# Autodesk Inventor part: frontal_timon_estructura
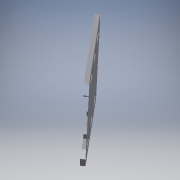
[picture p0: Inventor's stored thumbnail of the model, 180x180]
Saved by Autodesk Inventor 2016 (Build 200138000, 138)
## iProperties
Created: 2017-06
Part Number: frontal_timon_estructura
Material: Generic
Document SubType Name: Modeling
Designer: laboratorioesan
Density: 1 g/cm^3
Appearance: Default
Author: laboratorioesan
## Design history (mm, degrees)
sketch "Sketch1"
  geometry: L1 (-29.189, -4.822)-(-51.614, 22.05) reference; L2 (-47.008, 25.895)-(-22.981, -2.897) reference; L3 (-10.409, -15.199)-(29.692, 18.266) reference; L4 (-43.009, -16.355)-(-65.434, 10.517) reference; L5 (-70.041, 6.673)-(-45.325, -22.944) reference; L6 (-47.008, 25.895)-(-70.041, 6.673) reference; L7 (-31.652, 38.709)-(-432.262, 518.759); L8 (-432.262, 518.759)-(-420.361, 528.69); L9 (-420.361, 528.69)-(-19.752, 48.64); L10 (-31.652, 38.709)-(-19.752, 48.64); L11 (-1131.104, 152.556)-(-641.104, 152.556) reference; L12 (-220.057, 288.665)-(-231.957, 278.734); 1 further point
  constraints: 18 end point, 2 midpoint, 1 parallel, 1 perpendicular, 12 other
  dimensions: "d0" = 20 distance between parallel lines of L7 L2; "d1" = 15.5 distance of L7.end L8.end
extrude "Extrusion1" new body sketch "Sketch1" stored distance "d2" = 200; taper "d3" = 0 deg
sketch "Sketch2"
  geometry: L1 (200, 0)-(0, 0) reference; L2 (0, -312.624)-(0, 0) reference; L3 (200, -312.624)-(0, -312.624) reference; L4 (200, 0)-(200, -312.624) reference; L5 (20, -40)-(35.5, -40); L6 (35.5, -40)-(35.5, -90); L7 (35.5, -90)-(20, -90); L8 (20, -90)-(20, -40); L9 (20, -140)-(35.5, -140); L10 (35.5, -140)-(35.5, -190); L11 (35.5, -190)-(20, -190); L12 (20, -190)-(20, -140); L13 (20, -240)-(35.5, -240); L14 (35.5, -240)-(35.5, -290); L15 (35.5, -290)-(20, -290); L16 (20, -290)-(20, -240); L17 (164.5, -40)-(180, -40); L18 (180, -40)-(180, -90); L19 (180, -90)-(164.5, -90); L20 (164.5, -90)-(164.5, -40); L21 (164.5, -140)-(180, -140); L22 (180, -140)-(180, -190); L23 (180, -190)-(164.5, -190); L24 (164.5, -190)-(164.5, -140); L25 (164.5, -240)-(180, -240); L26 (180, -240)-(180, -290); L27 (180, -290)-(164.5, -290); L28 (164.5, -290)-(164.5, -240); 1 further point
  constraints: 48 end point, 12 parallel, 6 horizontal, 6 horizontal alignment, 6 perpendicular, 5 vertical alignment, 4 point on line
  dimensions: "d4" = 15.5 distance of L6.end L7.end; "d5" = 50 distance of L5.end L6.end; "d6" = 20 horizontal distance of L1.end L5.start; "d7" = 40 vertical distance of L1.end L5.start; "d8" = 50 distance of L9.end L10.end; "d9" = 50 distance between parallel lines of L9 L7; "d10" = 50 distance of L13.end L14.end; "d11" = 50 distance between parallel lines of L13 L11; "d12" = 15.5 distance of L18.end L19.end; "d13" = 20 horizontal distance of L1.start L17.end
extrude "Extrusion2" cut sketch "Sketch2" distance "d14" = 15.5; taper "d15" = 0 deg
sketch "Sketch3"
  geometry: L1 (-318.5, -237.627)-(518.5, -237.627) reference; L2 (164.5, -190)-(164.5, -140) reference; L3 (164.5, -140)-(180, -140) reference; L4 (180, -140)-(180, -190) reference; L5 (180, -190)-(164.5, -190) reference; L6 (20, -290)-(20, -240) reference; L7 (20, -240)-(35.5, -240) reference; L8 (35.5, -240)-(35.5, -290) reference; L9 (35.5, -290)-(20, -290) reference; L10 (20, -90)-(20, -40) reference; L11 (20, -40)-(35.5, -40) reference; L12 (35.5, -40)-(35.5, -90) reference; L13 (35.5, -90)-(20, -90) reference; L14 (20, -190)-(20, -140) reference; L15 (20, -140)-(35.5, -140) reference; L16 (35.5, -140)-(35.5, -190) reference; L17 (35.5, -190)-(20, -190) reference; L18 (164.5, -90)-(164.5, -40) reference; L19 (164.5, -40)-(180, -40) reference; L20 (180, -40)-(180, -90) reference; L21 (180, -90)-(164.5, -90) reference; L22 (164.5, -290)-(164.5, -240) reference; L23 (164.5, -240)-(180, -240) reference; L24 (180, -240)-(180, -290) reference; L25 (180, -290)-(164.5, -290) reference; L26 (200, 0)-(0, 0) reference; L27 (0, -312.624)-(0, 0) reference; L28 (200, -312.624)-(0, -312.624) reference; L29 (200, 0)-(200, -312.624) reference; L30 (0, -312.624)-(200, -312.624); L31 (200, -312.624)-(200, -452.624); L32 (200, -452.624)-(0, -452.624); L33 (0, -452.624)-(0, -312.624); L34 (20, -350)-(35.5, -350); L35 (35.5, -350)-(35.5, -400); L36 (35.5, -400)-(20, -400); L37 (20, -400)-(20, -350); L38 (164.5, -350)-(180, -350); L39 (180, -350)-(180, -400); L40 (180, -400)-(164.5, -400); L41 (164.5, -400)-(164.5, -350); 1 further point
  constraints: 24 end point, 6 parallel, 3 horizontal, 3 perpendicular, 1 horizontal alignment
  dimensions: "d16" = 140 distance of L30.end L31.end; "d17" = 50 distance of L34.end L35.end; "d18" = 60 distance of L6.start L34.start; "d19" = 50 distance of L38.end L39.end
extrude "Extrusion3" join sketch "Sketch3" distance "d20" = 15.5; taper "d21" = 0 deg
workplane "Work Plane1"
sketch "Sketch4"
  geometry: L1 (432.262, 518.759)-(142.256, 171.246) reference; L2 (432.262, 518.759)-(420.361, 528.69) reference; L3 (420.361, 528.69)-(130.356, 181.177) reference; L4 (130.356, 181.177)-(142.256, 171.246) reference; L5 (-32.55, 77.056)-(199.272, 77.056) reference; L6 (142.256, 171.246)-(63.654, 77.056); L7 (51.753, 86.987)-(130.356, 181.177); L8 (51.753, 86.987)-(63.654, 77.056); 1 further point
  constraints: 6 end point, 1 parallel, 1 perpendicular, 1 point on line
extrude "Extrusion4" join sketch "Sketch4" stored distance "d22" = 880; taper "d23" = 0 deg
fillet "Fillet1" dims "d24" = 120
fillet "Fillet2" dims "d25" = 50
body "Solid1"
node "Reference1"
node "Reference2"
node "Reference3"
node "Projected Loop1"
node "Reference4"
node "Projected Loop2"
node "Projected Loop3"
node "Reference5"
